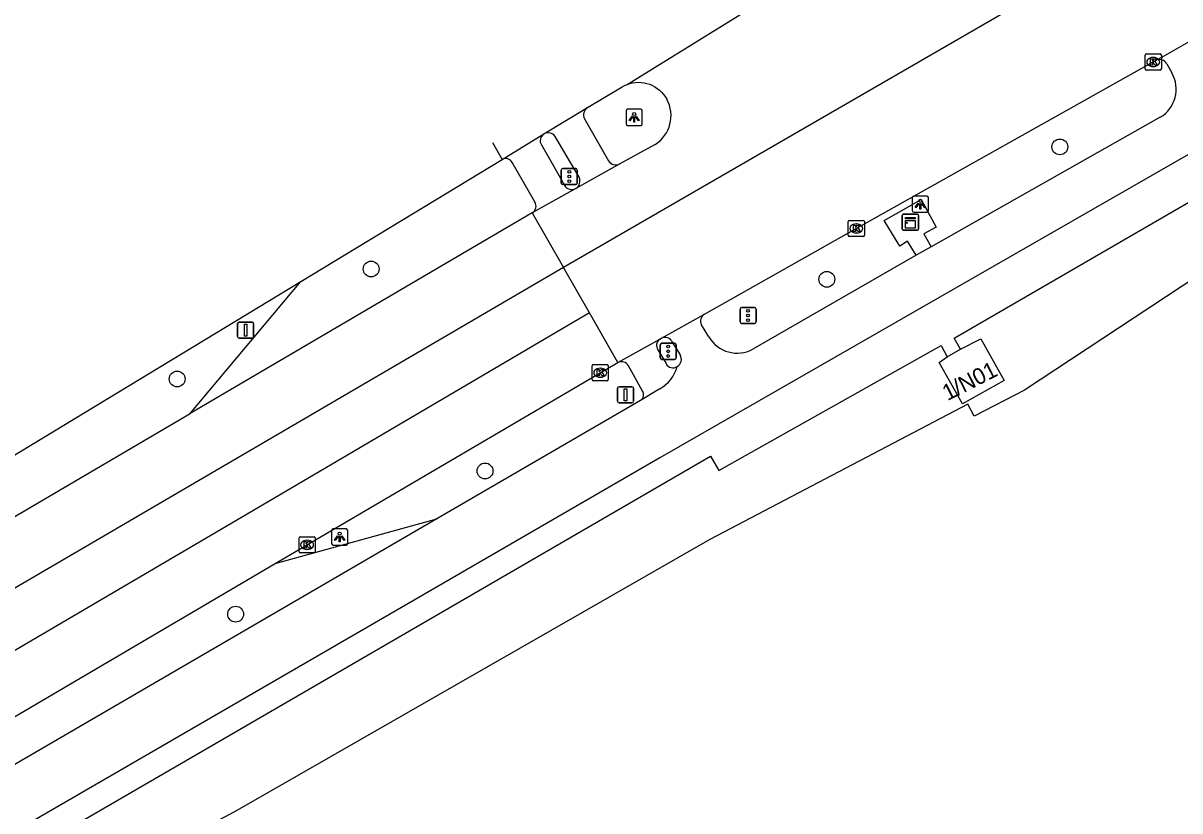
# Model space of a CAD drawing. Extents: x 158132 to 159658, y 385257 to 387209.
# Drawn here: x 158601.6 to 158673.1, y 387050.5 to 387099.3 of the extents above; entities that cross this region are included whole.
import ezdxf

# ---------------------------------------------------------------- set-up
doc = ezdxf.new("R2010")
doc.units = 0
for name, color, linetype in [('IMGEO_Berm_groen', 7, 'Continuous'), ('IMGEO_Boom', 7, 'Continuous'), ('IMGEO_Fietspad_gesloten', 7, 'Continuous'), ('IMGEO_Fietspad_open', 7, 'Continuous'), ('IMGEO_Gemengd_bos', 7, 'Continuous'), ('IMGEO_Kast', 7, 'Continuous'), ('IMGEO_Kolk', 7, 'Continuous'), ('IMGEO_Lichtpunt', 7, 'Continuous'), ('IMGEO_Pand', 7, 'Continuous'), ('IMGEO_Pand_nummerreeks', 7, 'Continuous'), ('IMGEO_Rijbaan_regionaal_gesloten', 7, 'Continuous'), ('IMGEO_Verkeersbordpaal', 7, 'Continuous'), ('IMGEO_Verkeersregelinstallatiepaal', 7, 'Continuous'), ('IMGEO_Voetpad_gesloten', 7, 'Continuous'), ('IMGEO_Voetpad_open', 7, 'Continuous')]:
    doc.layers.add(name, color=color, linetype=linetype)

msp = doc.modelspace()

# ---------------------------------------------------------------- linework, layer by layer
at = {"layer": 'IMGEO_Berm_groen'}
for points in [[(158611.895, 387075.125), (158618.74, 387083.291)], [(158617.156, 387065.84), (158627.156, 387068.604)]]:
    msp.add_lwpolyline(points, dxfattribs=at)
at = {"layer": 'IMGEO_Boom'}
for centre in [(158665.7, 387091.614), (158623.088, 387084.063), (158651.283, 387083.422), (158611.082, 387077.255), (158630.136, 387071.568), (158614.7, 387062.705)]:
    msp.add_circle(centre, 0.489, dxfattribs=at)
at = {"layer": 'IMGEO_Fietspad_gesloten'}
for points in [[(158823.804, 387176.598), (158776.889, 387150.893), (158732.48, 387123.894), (158722.886, 387118.521), (158715.758, 387114.904), (158709.569, 387111.62), (158675.022, 387091.93), (158640.944, 387072.387), (158595.958, 387046.323), (158573.791, 387032.697), (158546.099, 387014.697), (158529.924, 387003.032), (158525.945, 387000), (158514.127, 386990.649), (158513.131, 386989.793), (158506.548, 386984.134), (158500, 386978.134), (158499.211, 386977.385), (158490.608, 386969.265)], [(158672.322, 387096.753), (158672.633, 387096.191)], [(158671.92, 387093.449), (158657.749, 387085.442)], [(158656.81, 387084.909), (158646.715, 387079.103)], [(158657.749, 387085.442), (158656.81, 387084.909)], [(158643.987, 387079.857), (158643.534, 387080.605)], [(158641.68, 387079.598), (158642.201, 387078.743)], [(158640.95, 387076.647), (158639.754, 387075.926)], [(158639.754, 387075.926), (158627.156, 387068.604)], [(158627.156, 387068.604), (158591.691, 387047.993)]]:
    msp.add_lwpolyline(points, dxfattribs=at)
for centre, radius, start, end in [((158671.869, 387096.494), 0.522, 29.72072, 112.35811), ((158670.873, 387095.185), 2.027, 301.09946, 29.74898), ((158643.976, 387080.847), 0.504, 121.43961, 208.7294), ((158641.269, 387079.347), 0.481, 31.42003, 116.71332), ((158645.742, 387080.893), 2.038, 210.56163, 298.53752), ((158641.78, 387078.469), 0.502, 299.56439, 33.0477), ((158639.822, 387078.636), 2.287, 299.54918, 344.70086)]:
    msp.add_arc(centre, radius, start, end, dxfattribs=at)
at = {"layer": 'IMGEO_Fietspad_open'}
for points in [[(158636.297, 387093.355), (158637.78, 387090.754)], [(158635.955, 387089.734), (158634.48, 387092.259)]]:
    msp.add_lwpolyline(points, dxfattribs=at)
for centre, radius, start, end in [((158636.759, 387093.607), 0.526, 123.54489, 208.65592), ((158634.04, 387091.937), 0.545, 36.14621, 118.1885), ((158638.227, 387091.013), 0.516, 210.06336, 298.26499), ((158635.49, 387089.496), 0.522, 299.32442, 27.11029)]:
    msp.add_arc(centre, radius, start, end, dxfattribs=at)
at = {"layer": 'IMGEO_Gemengd_bos'}
msp.add_lwpolyline([(158703.822, 387101.712), (158681.036, 387088.113), (158663.513, 387076.566), (158660.407, 387074.962), (158660.01, 387075.699), (158644.038, 387067.333), (158614.63, 387050.481), (158601.872, 387043.698)], dxfattribs=at)
at = {"layer": 'IMGEO_Kast'}
for p, q in [((158655.954, 387086.529), (158655.954, 387087.37)), ((158655.954, 387087.37), (158655.954, 387086.529)), ((158656.029, 387087.454), (158656.87, 387087.454)), ((158656.87, 387087.454), (158656.029, 387087.454)), ((158656.954, 387087.379), (158656.954, 387086.538)), ((158656.954, 387086.538), (158656.954, 387087.379)), ((158656.879, 387086.454), (158656.038, 387086.454)), ((158656.038, 387086.454), (158656.879, 387086.454))]:
    msp.add_line(p, q, dxfattribs=at)
for points in [[(158656.149, 387087.244), (158656.749, 387087.244), (158656.749, 387087.159), (158656.149, 387087.159), (158656.149, 387087.244)], [(158656.149, 387087.069), (158656.749, 387087.069), (158656.749, 387086.58), (158656.149, 387086.58), (158656.149, 387087.069)]]:
    msp.add_lwpolyline(points, dxfattribs=at)
msp.add_circle((158656.233, 387086.918), 0.0377, dxfattribs=at)
for centre, start, end in [((158656.032, 387087.376), 92.4484, 184.28452), ((158656.032, 387087.376), 92.4484, 184.28452), ((158656.876, 387087.376), 2.4484, 94.28452), ((158656.876, 387087.376), 2.4484, 94.28452), ((158656.032, 387086.532), 182.4484, 274.28452), ((158656.032, 387086.532), 182.4484, 274.28452), ((158656.876, 387086.532), 272.4484, 4.28452), ((158656.876, 387086.532), 272.4484, 4.28452)]:
    msp.add_arc(centre, 0.0779, start, end, dxfattribs=at)
at = {"layer": 'IMGEO_Kolk'}
for p, q in [((158670.982, 387096.441), (158670.982, 387097.293)), ((158671.057, 387097.367), (158671.909, 387097.367)), ((158671.47, 387097.147), (158671.495, 387097.147)), ((158671.983, 387097.293), (158671.983, 387096.441)), ((158671.909, 387096.367), (158671.057, 387096.367)), ((158671.493, 387096.587), (158671.468, 387096.587)), ((158652.606, 387086.145), (158652.606, 387086.997)), ((158652.681, 387087.071), (158653.533, 387087.071)), ((158653.607, 387086.997), (158653.607, 387086.145)), ((158653.117, 387086.291), (158653.092, 387086.291)), ((158653.094, 387086.851), (158653.119, 387086.851)), ((158653.533, 387086.071), (158652.681, 387086.071)), ((158636.762, 387077.218), (158636.762, 387078.07)), ((158636.837, 387078.144), (158637.689, 387078.144)), ((158637.25, 387077.924), (158637.275, 387077.924)), ((158637.763, 387078.07), (158637.763, 387077.218)), ((158637.689, 387077.144), (158636.837, 387077.144)), ((158637.273, 387077.364), (158637.248, 387077.364)), ((158618.625, 387066.57), (158618.625, 387067.422)), ((158618.7, 387067.496), (158619.552, 387067.496)), ((158619.113, 387067.276), (158619.138, 387067.276)), ((158619.626, 387067.422), (158619.626, 387066.57)), ((158619.552, 387066.496), (158618.7, 387066.496)), ((158619.136, 387066.716), (158619.111, 387066.716))]:
    msp.add_line(p, q, dxfattribs=at)
for points in [[(158670.982, 387096.441), (158670.982, 387097.293)], [(158671.057, 387097.367), (158671.909, 387097.367)], [(158671.303, 387097.067), (158671.426, 387097.067), (158671.426, 387096.916), (158671.556, 387097.067), (158671.72, 387097.067), (158671.574, 387096.916), (158671.727, 387096.667), (158671.575, 387096.667), (158671.49, 387096.831), (158671.426, 387096.764), (158671.426, 387096.667), (158671.303, 387096.667), (158671.303, 387097.067)], [(158671.983, 387097.293), (158671.983, 387096.441)], [(158671.909, 387096.367), (158671.057, 387096.367)], [(158652.606, 387086.145), (158652.606, 387086.997)], [(158652.681, 387087.071), (158653.533, 387087.071)], [(158653.607, 387086.997), (158653.607, 387086.145)], [(158652.927, 387086.771), (158653.05, 387086.771), (158653.05, 387086.62), (158653.18, 387086.771), (158653.344, 387086.771), (158653.198, 387086.62), (158653.351, 387086.371), (158653.199, 387086.371), (158653.114, 387086.535), (158653.05, 387086.468), (158653.05, 387086.371), (158652.927, 387086.371), (158652.927, 387086.771)], [(158653.533, 387086.071), (158652.681, 387086.071)], [(158636.762, 387077.218), (158636.762, 387078.07)], [(158636.837, 387078.144), (158637.689, 387078.144)], [(158637.083, 387077.844), (158637.206, 387077.844), (158637.206, 387077.693), (158637.336, 387077.844), (158637.5, 387077.844), (158637.354, 387077.693), (158637.507, 387077.444), (158637.355, 387077.444), (158637.27, 387077.608), (158637.206, 387077.541), (158637.206, 387077.444), (158637.083, 387077.444), (158637.083, 387077.844)], [(158637.763, 387078.07), (158637.763, 387077.218)], [(158637.689, 387077.144), (158636.837, 387077.144)], [(158618.625, 387066.57), (158618.625, 387067.422)], [(158618.7, 387067.496), (158619.552, 387067.496)], [(158618.946, 387067.196), (158619.069, 387067.196), (158619.069, 387067.045), (158619.199, 387067.196), (158619.363, 387067.196), (158619.217, 387067.045), (158619.37, 387066.796), (158619.218, 387066.796), (158619.133, 387066.96), (158619.069, 387066.893), (158619.069, 387066.796), (158618.946, 387066.796), (158618.946, 387067.196)], [(158619.626, 387067.422), (158619.626, 387066.57)], [(158619.552, 387066.496), (158618.7, 387066.496)]]:
    msp.add_lwpolyline(points, dxfattribs=at)
for centre, start, end in [((158671.059, 387097.291), 91.55205, 178.44795), ((158671.059, 387097.291), 91.55205, 178.44795), ((158671.907, 387097.291), 1.55205, 88.44795), ((158671.907, 387097.291), 1.55205, 88.44795), ((158671.059, 387096.443), 181.55205, 268.44795), ((158671.059, 387096.443), 181.55205, 268.44795), ((158671.907, 387096.443), 271.55205, 358.44795), ((158671.907, 387096.443), 271.55205, 358.44795), ((158652.683, 387086.995), 91.55205, 178.44795), ((158652.683, 387086.995), 91.55205, 178.44795), ((158653.531, 387086.995), 1.55205, 88.44795), ((158653.531, 387086.995), 1.55205, 88.44795), ((158652.683, 387086.147), 181.55205, 268.44795), ((158652.683, 387086.147), 181.55205, 268.44795), ((158653.531, 387086.147), 271.55205, 358.44795), ((158653.531, 387086.147), 271.55205, 358.44795), ((158636.839, 387078.068), 91.55205, 178.44795), ((158636.839, 387078.068), 91.55205, 178.44795), ((158637.687, 387078.068), 1.55205, 88.44795), ((158637.687, 387078.068), 1.55205, 88.44795), ((158636.839, 387077.22), 181.55205, 268.44795), ((158636.839, 387077.22), 181.55205, 268.44795), ((158637.687, 387077.22), 271.55205, 358.44795), ((158637.687, 387077.22), 271.55205, 358.44795), ((158618.702, 387067.42), 91.55205, 178.44795), ((158618.702, 387067.42), 91.55205, 178.44795), ((158619.55, 387067.42), 1.55205, 88.44795), ((158619.55, 387067.42), 1.55205, 88.44795), ((158618.702, 387066.572), 181.55205, 268.44795), ((158618.702, 387066.572), 181.55205, 268.44795), ((158619.55, 387066.572), 271.55205, 358.44795), ((158619.55, 387066.572), 271.55205, 358.44795)]:
    msp.add_arc(centre, 0.0765, start, end, dxfattribs=at)
for centre, major_axis, ratio, start_param, end_param in [((158671.469, 387096.867), (-0.387, 0.002), 0.722429, 4.712389, 7.853982), ((158671.494, 387096.867), (-0.39, 0.002), 0.717154, 1.570796, 4.712389), ((158653.093, 387086.571), (-0.387, 0.002), 0.722429, 4.712389, 7.853982), ((158653.118, 387086.571), (-0.39, 0.002), 0.717154, 1.570796, 4.712389), ((158637.249, 387077.644), (-0.387, 0.002), 0.722429, 4.712389, 7.853982), ((158637.274, 387077.644), (-0.39, 0.002), 0.717154, 1.570796, 4.712389), ((158619.112, 387066.996), (-0.387, 0.002), 0.722429, 4.712389, 7.853982), ((158619.137, 387066.996), (-0.39, 0.002), 0.717154, 1.570796, 4.712389)]:
    msp.add_ellipse(centre, major_axis=major_axis, ratio=ratio, start_param=start_param, end_param=end_param, dxfattribs=at)
at = {"layer": 'IMGEO_Lichtpunt'}
for p, q in [((158638.864, 387093.85), (158638.864, 387093.043)), ((158638.864, 387093.85), (158638.864, 387093.043)), ((158639.766, 387093.945), (158638.958, 387093.945)), ((158639.766, 387093.945), (158638.958, 387093.945)), ((158639.86, 387093.043), (158639.86, 387093.85)), ((158639.86, 387093.043), (158639.86, 387093.85)), ((158638.958, 387092.949), (158639.766, 387092.949)), ((158638.958, 387092.949), (158639.766, 387092.949)), ((158656.572, 387088.479), (158656.572, 387087.672)), ((158656.572, 387088.479), (158656.572, 387087.672)), ((158657.474, 387088.574), (158656.666, 387088.574)), ((158657.474, 387088.574), (158656.666, 387088.574)), ((158657.568, 387087.672), (158657.568, 387088.479)), ((158657.568, 387087.672), (158657.568, 387088.479)), ((158656.666, 387087.578), (158657.474, 387087.578)), ((158656.666, 387087.578), (158657.474, 387087.578)), ((158620.639, 387067.887), (158620.639, 387067.08)), ((158620.639, 387067.887), (158620.639, 387067.08)), ((158621.541, 387067.982), (158620.733, 387067.982)), ((158621.541, 387067.982), (158620.733, 387067.982)), ((158621.635, 387067.08), (158621.635, 387067.887)), ((158621.635, 387067.08), (158621.635, 387067.887)), ((158620.733, 387066.986), (158621.541, 387066.986)), ((158620.733, 387066.986), (158621.541, 387066.986))]:
    msp.add_line(p, q, dxfattribs=at)
for points in [[(158639.238, 387093.514), (158639.277, 387093.486), (158639.089, 387093.224), (158639.051, 387093.251), (158639.238, 387093.514)], [(158639.34, 387093.466), (158639.387, 387093.466), (158639.387, 387093.144), (158639.34, 387093.144), (158639.34, 387093.466)], [(158639.45, 387093.486), (158639.488, 387093.513), (158639.675, 387093.251), (158639.636, 387093.223), (158639.45, 387093.486)], [(158656.946, 387088.143), (158656.985, 387088.115), (158656.797, 387087.853), (158656.759, 387087.88), (158656.946, 387088.143)], [(158657.048, 387088.095), (158657.095, 387088.095), (158657.095, 387087.773), (158657.048, 387087.773), (158657.048, 387088.095)], [(158657.158, 387088.115), (158657.196, 387088.142), (158657.383, 387087.88), (158657.344, 387087.852), (158657.158, 387088.115)], [(158621.013, 387067.551), (158621.052, 387067.523), (158620.864, 387067.261), (158620.826, 387067.288), (158621.013, 387067.551)], [(158621.115, 387067.503), (158621.162, 387067.503), (158621.162, 387067.181), (158621.115, 387067.181), (158621.115, 387067.503)], [(158621.225, 387067.523), (158621.263, 387067.55), (158621.45, 387067.288), (158621.411, 387067.26), (158621.225, 387067.523)]]:
    msp.add_lwpolyline(points, dxfattribs=at)
for centre in [(158639.363, 387093.648), (158657.071, 387088.277), (158621.138, 387067.685)]:
    msp.add_circle(centre, 0.0994, dxfattribs=at)
for centre, start, end in [((158638.958, 387093.85), 90, 180), ((158638.958, 387093.85), 90, 180), ((158639.766, 387093.85), 0, 90), ((158639.766, 387093.85), 0, 90), ((158638.958, 387093.043), 180, 270), ((158638.958, 387093.043), 180, 270), ((158639.766, 387093.043), 270, 0), ((158639.766, 387093.043), 270, 360), ((158656.666, 387088.479), 90, 180), ((158656.666, 387088.479), 90, 180), ((158657.474, 387088.479), 0, 90), ((158657.474, 387088.479), 0, 90), ((158656.666, 387087.672), 180, 270), ((158656.666, 387087.672), 180, 270), ((158657.474, 387087.672), 270, 0), ((158657.474, 387087.672), 270, 360), ((158620.733, 387067.887), 90, 180), ((158620.733, 387067.887), 90, 180), ((158621.541, 387067.887), 0, 90), ((158621.541, 387067.887), 0, 90), ((158620.733, 387067.08), 180, 270), ((158620.733, 387067.08), 180, 270), ((158621.541, 387067.08), 270, 0), ((158621.541, 387067.08), 270, 360)]:
    msp.add_arc(centre, 0.0946, start, end, dxfattribs=at)
at = {"layer": 'IMGEO_Pand'}
for points in [[(158659.554, 387079.092), (158660.809, 387079.732), (158662.255, 387077.168), (158659.686, 387075.719), (158658.24, 387078.283), (158658.738, 387078.625)], [(158658.738, 387078.625), (158659.554, 387079.092)]]:
    msp.add_lwpolyline(points, dxfattribs=at)
at = {"layer": 'IMGEO_Rijbaan_regionaal_gesloten'}
for points in [[(158638.923, 387095.483), (158660.935, 387109.107)], [(158665.435, 387101.784), (158665.391, 387101.739), (158634.991, 387084.15)], [(158671.67, 387096.977), (158672.057, 387097.196), (158674.36, 387098.497)], [(158643.713, 387081.277), (158653.107, 387086.573), (158671.483, 387096.869), (158671.67, 387096.977)], [(158636.468, 387094.046), (158638.612, 387095.334), (158638.758, 387095.412), (158638.923, 387095.483)], [(158638.923, 387095.483), (158639.093, 387095.538), (158639.267, 387095.578), (158639.444, 387095.602), (158639.622, 387095.611), (158639.801, 387095.603), (158639.978, 387095.58), (158640.152, 387095.541), (158640.322, 387095.486), (158640.487, 387095.416), (158640.645, 387095.332), (158640.794, 387095.234), (158640.935, 387095.124), (158641.064, 387095.001), (158641.183, 387094.867), (158641.288, 387094.723), (158641.381, 387094.57)], [(158633.782, 387092.418), (158636.468, 387094.046)], [(158631.19, 387090.837), (158633.782, 387092.418)], [(158630.595, 387091.882), (158631.19, 387090.837)], [(158640.66, 387091.765), (158638.471, 387090.558)], [(158618.74, 387083.291), (158631.19, 387090.837)], [(158638.471, 387090.558), (158635.746, 387089.041)], [(158635.746, 387089.041), (158633.046, 387087.541)], [(158633.046, 387087.541), (158611.895, 387075.125)], [(158633.046, 387087.541), (158634.991, 387084.15)], [(158634.991, 387084.15), (158606.55, 387067.536), (158577.06, 387050.309), (158556.671, 387038.038), (158547.175, 387032.064)], [(158636.602, 387081.343), (158634.991, 387084.15)], [(158567.106, 387051.889), (158575.407, 387057.027), (158618.74, 387083.291)], [(158636.602, 387081.343), (158615.074, 387068.69), (158601.791, 387060.883), (158568.259, 387041.175), (158561.926, 387037.339), (158555.122, 387033.014), (158550.017, 387029.416), (158544.138, 387025.142), (158527.373, 387012.736), (158505.629, 386996.548), (158499.529, 386992.007), (158493.05, 386986.916), (158477.338, 386973.816), (158474.038, 386970.817), (158458.566, 386956.347), (158449.5, 386947.868), (158432.355, 386931.617), (158423.441, 386923.167), (158413.031, 386913.162), (158402.684, 386902.782), (158396.042, 386896.016), (158388.135, 386887.962)], [(158638.361, 387078.278), (158636.602, 387081.343)], [(158641.053, 387079.777), (158643.713, 387081.277)], [(158640.946, 387079.718), (158641.053, 387079.777)], [(158638.361, 387078.278), (158640.946, 387079.718)], [(158617.156, 387065.84), (158637.262, 387077.646), (158638.361, 387078.278)], [(158569.694, 387050.352), (158611.895, 387075.125)], [(158566.678, 387036.17), (158567.262, 387036.494), (158581.897, 387045.137), (158599.21, 387055.303), (158617.156, 387065.84)]]:
    msp.add_lwpolyline(points, dxfattribs=at)
msp.add_arc((158639.528, 387093.551), 2.115, 302.37467, 28.79473, dxfattribs=at)
at = {"layer": 'IMGEO_Verkeersbordpaal'}
for p, q in [((158614.825, 387079.88), (158614.825, 387080.68)), ((158614.825, 387080.68), (158614.825, 387079.88)), ((158614.925, 387080.78), (158615.715, 387080.78)), ((158615.715, 387080.78), (158614.925, 387080.78)), ((158615.815, 387080.68), (158615.815, 387079.88)), ((158615.815, 387079.88), (158615.815, 387080.68)), ((158615.715, 387079.78), (158614.925, 387079.78)), ((158614.925, 387079.78), (158615.715, 387079.78)), ((158638.33, 387075.88), (158638.33, 387076.68)), ((158638.33, 387076.68), (158638.33, 387075.88)), ((158638.43, 387076.78), (158639.22, 387076.78)), ((158639.22, 387076.78), (158638.43, 387076.78)), ((158639.32, 387076.68), (158639.32, 387075.88)), ((158639.32, 387075.88), (158639.32, 387076.68)), ((158639.22, 387075.78), (158638.43, 387075.78)), ((158638.43, 387075.78), (158639.22, 387075.78))]:
    msp.add_line(p, q, dxfattribs=at)
for points in [[(158615.245, 387080.655), (158615.395, 387080.655), (158615.395, 387079.905), (158615.245, 387079.905), (158615.245, 387080.655)], [(158638.75, 387076.655), (158638.9, 387076.655), (158638.9, 387075.905), (158638.75, 387075.905), (158638.75, 387076.655)]]:
    msp.add_lwpolyline(points, dxfattribs=at)
for centre, start, end in [((158614.925, 387080.68), 90, 180), ((158614.925, 387080.68), 90, 180), ((158615.715, 387080.68), 0, 90), ((158615.715, 387080.68), 360, 90), ((158614.925, 387079.88), 180, 270), ((158614.925, 387079.88), 180, 270), ((158615.715, 387079.88), 270, 0), ((158615.715, 387079.88), 270, 0), ((158638.43, 387076.68), 90, 180), ((158638.43, 387076.68), 90, 180), ((158639.22, 387076.68), 0, 90), ((158639.22, 387076.68), 360, 90), ((158638.43, 387075.88), 180, 270), ((158638.43, 387075.88), 180, 270), ((158639.22, 387075.88), 270, 0), ((158639.22, 387075.88), 270, 0)]:
    msp.add_arc(centre, 0.1, start, end, dxfattribs=at)
at = {"layer": 'IMGEO_Verkeersregelinstallatiepaal'}
for p, q in [((158634.855, 387089.38), (158634.855, 387090.18)), ((158634.855, 387090.18), (158634.855, 387089.38)), ((158634.955, 387090.28), (158635.745, 387090.28)), ((158635.745, 387090.28), (158634.955, 387090.28)), ((158635.845, 387090.18), (158635.845, 387089.38)), ((158635.845, 387089.38), (158635.845, 387090.18)), ((158635.745, 387089.28), (158634.955, 387089.28)), ((158634.955, 387089.28), (158635.745, 387089.28)), ((158645.913, 387080.785), (158645.913, 387081.585)), ((158645.913, 387081.585), (158645.913, 387080.785)), ((158646.013, 387081.685), (158646.803, 387081.685)), ((158646.803, 387081.685), (158646.013, 387081.685)), ((158646.903, 387081.585), (158646.903, 387080.785)), ((158646.903, 387080.785), (158646.903, 387081.585)), ((158646.803, 387080.685), (158646.013, 387080.685)), ((158646.013, 387080.685), (158646.803, 387080.685)), ((158640.976, 387078.569), (158640.976, 387079.369)), ((158640.976, 387079.369), (158640.976, 387078.569)), ((158641.076, 387079.469), (158641.866, 387079.469)), ((158641.866, 387079.469), (158641.076, 387079.469)), ((158641.966, 387079.369), (158641.966, 387078.569)), ((158641.966, 387078.569), (158641.966, 387079.369)), ((158641.866, 387078.469), (158641.076, 387078.469)), ((158641.076, 387078.469), (158641.866, 387078.469))]:
    msp.add_line(p, q, dxfattribs=at)
for centre in [(158635.35, 387090.07), (158635.35, 387089.78), (158635.35, 387089.49), (158646.408, 387081.475), (158646.408, 387081.185), (158646.408, 387080.895), (158641.471, 387079.259), (158641.471, 387078.969), (158641.471, 387078.679)]:
    msp.add_circle(centre, 0.085, dxfattribs=at)
for centre, start, end in [((158634.955, 387090.18), 90, 180), ((158634.955, 387090.18), 90, 180), ((158635.745, 387090.18), 0, 90), ((158635.745, 387090.18), 360, 90), ((158634.955, 387089.38), 180, 270), ((158634.955, 387089.38), 180, 270), ((158635.745, 387089.38), 270, 0), ((158635.745, 387089.38), 270, 0), ((158646.013, 387081.585), 90, 180), ((158646.013, 387081.585), 90, 180), ((158646.803, 387081.585), 0, 90), ((158646.803, 387081.585), 360, 90), ((158646.013, 387080.785), 180, 270), ((158646.013, 387080.785), 180, 270), ((158646.803, 387080.785), 270, 0), ((158646.803, 387080.785), 270, 0), ((158641.076, 387079.369), 90, 180), ((158641.076, 387079.369), 90, 180), ((158641.866, 387079.369), 0, 90), ((158641.866, 387079.369), 360, 90), ((158641.076, 387078.569), 180, 270), ((158641.076, 387078.569), 180, 270), ((158641.866, 387078.569), 270, 0), ((158641.866, 387078.569), 270, 0)]:
    msp.add_arc(centre, 0.1, start, end, dxfattribs=at)
at = {"layer": 'IMGEO_Voetpad_gesloten'}
for points in [[(158659.554, 387079.092), (158659.165, 387079.773), (158676.28, 387089.711), (158679.065, 387091.306), (158713.234, 387110.714)], [(158574.561, 387031.328), (158596.687, 387045.001), (158644.089, 387072.48), (158644.611, 387071.596), (158658.366, 387079.32), (158658.738, 387078.625)]]:
    msp.add_lwpolyline(points, dxfattribs=at)
at = {"layer": 'IMGEO_Voetpad_open'}
for points in [[(158633.622, 387091.735), (158635.051, 387089.238)], [(158633.218, 387088.207), (158631.815, 387090.646)], [(158656.81, 387084.909), (158656.284, 387085.786), (158655.792, 387085.474), (158654.841, 387087.064), (158657.127, 387088.351), (158658.041, 387086.659), (158657.293, 387086.246), (158657.749, 387085.442)], [(158640.837, 387079.068), (158641.339, 387078.208)], [(158639.864, 387076.552), (158639.003, 387078.072)]]:
    msp.add_lwpolyline(points, dxfattribs=at)
for centre, radius, start, end in [((158634.041, 387091.997), 0.495, 121.64435, 211.98686), ((158631.408, 387090.432), 0.46, 27.70921, 118.30448), ((158635.498, 387089.492), 0.514, 209.57214, 298.77676), ((158632.813, 387087.956), 0.476, 299.30683, 31.73176), ((158641.201, 387079.341), 0.455, 124.03856, 216.92247), ((158638.577, 387077.847), 0.482, 27.81234, 116.60767), ((158641.757, 387078.41), 0.464, 205.8051, 305.69235), ((158639.48, 387076.297), 0.461, 306.49222, 33.57537)]:
    msp.add_arc(centre, radius, start, end, dxfattribs=at)

# ---------------------------------------------------------------- texts
at = {"layer": 'IMGEO_Pand_nummerreeks'}
msp.add_text('1/N01', height=1, rotation=26.82015, dxfattribs=at).set_placement((158658.747, 387075.883))

doc.saveas('drawing.dxf')
